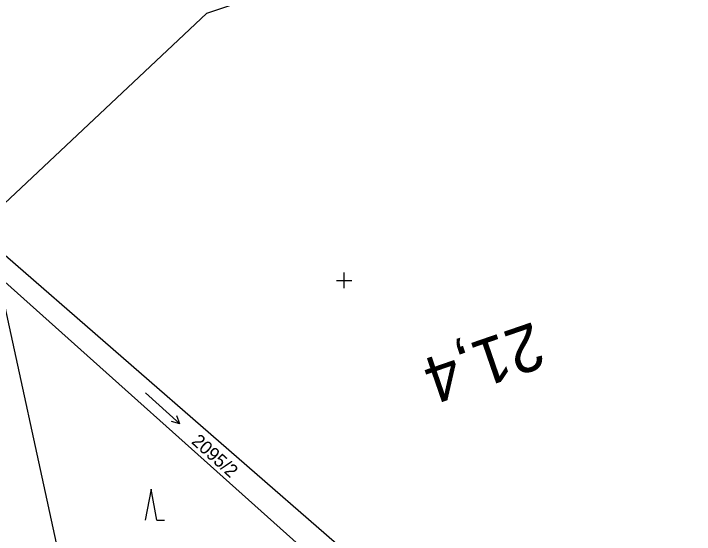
# Model space of a CAD drawing. Extents: x -776734 to -748832, y -1118122 to -976986.
# Drawn here: x -751042.8 to -750954.7, y -1114732.8 to -1114665.5 of the extents above; entities that cross this region are included whole.
import ezdxf

# ---------------------------------------------------------------- set-up
doc = ezdxf.new("R2010")
doc.units = 0
for name, color, linetype in [('KM_Hranice obce', 7, 'Continuous'), ('KM_Hranice parcel', 7, 'Continuous'), ('KM_Parcelní čísla', 7, 'Continuous'), ('KM_Značky kultur', 7, 'Continuous'), ('Level 61 Křížky', 7, 'Continuous'), ('SŽG Vrstva 53', 7, 'Continuous'), ('SŽG Vrstva 7', 7, 'Continuous')]:
    doc.layers.add(name, color=color, linetype=linetype)

msp = doc.modelspace()

# ---------------------------------------------------------------- linework, layer by layer
at = {"layer": 'KM_Hranice obce'}
msp.add_line((-750993.96, -1114740.18), (-751047.63, -1114693.52), dxfattribs=at)
msp.add_line((-750993.96, -1114740.18), (-751047.63, -1114693.52), dxfattribs=at)
at = {"layer": 'KM_Hranice parcel'}
for p in [(-751032.25, -1114756.83), (-750997.46, -1114741.7)]:
    msp.add_line(p, (-751044.76, -1114699.45), dxfattribs=at)
msp.add_lwpolyline([(-750903.28, -1114626.63), (-750977.55, -1114652.09), (-751017.8, -1114665.47), (-751047.63, -1114693.52)], dxfattribs=at)
at = {"layer": 'KM_Značky kultur'}
for p, q in [((-751025.712, -1114714.53), (-751021.254, -1114718.545)), ((-751021.254, -1114718.545), (-751021.644, -1114717.519)), ((-751021.254, -1114718.545), (-751022.315, -1114718.264)), ((-751024.98, -1114727.01), (-751025.73, -1114731.01)), ((-751024.23, -1114731.01), (-751024.98, -1114727.01)), ((-751024.23, -1114731.01), (-751023.234, -1114731.01))]:
    msp.add_line(p, q, dxfattribs=at)
at = {"layer": 'Level 61 Křížky'}
for p, q in [((-751000, -1114700), (-751000, -1114699)), ((-751000, -1114700), (-751000, -1114699)), ((-751001, -1114700), (-750999, -1114700)), ((-751001, -1114700), (-750999, -1114700)), ((-751000, -1114701), (-751000, -1114700)), ((-751000, -1114701), (-751000, -1114700))]:
    msp.add_line(p, q, dxfattribs=at)
at = {"layer": 'SŽG Vrstva 53'}
msp.add_lwpolyline([(-750804.97, -1114584.92), (-750894.76, -1114611.21), (-750899.97, -1114614.15), (-750906.35, -1114617.75), (-750903.28, -1114626.63), (-750977.55, -1114652.09), (-751017.8, -1114665.47), (-751047.63, -1114693.52)], dxfattribs=at)

# ---------------------------------------------------------------- texts
at = {"layer": 'KM_Parcelní čísla'}
msp.add_text('2095/2', height=1.7, rotation=318, dxfattribs=at).set_placement((-751019.8585, -1114720.9795))
at = {"layer": 'SŽG Vrstva 7'}
msp.add_text('21,4', height=6, rotation=199.014956, dxfattribs=at).set_placement((-750975.4872, -1114705.3126))

doc.saveas('drawing.dxf')
